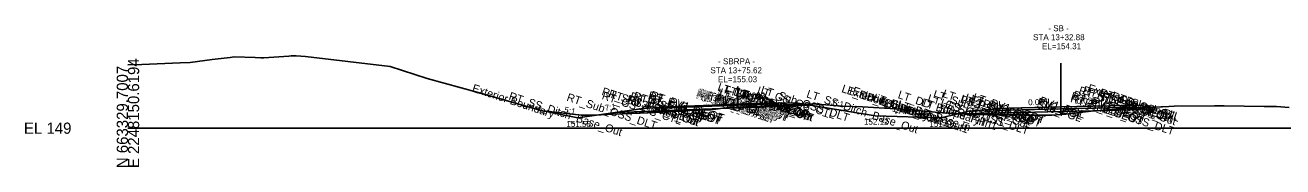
# Model space of a CAD drawing. Extents: x -26 to 2603, y -10 to 9566.
# Drawn here: x -25.7 to 288.7, y 6490.3 to 6525.8 of the extents above; entities that cross this region are included whole.
import ezdxf

# ---------------------------------------------------------------- set-up
doc = ezdxf.new("R2010")
doc.units = 0
for name, color, linetype in [('Default', 7, 'Continuous'), ('Exist Cross Section Cell', 7, 'Continuous'), ('Exist XS Ground Line', 7, 'Continuous'), ('Prop CMT Ditch DDE', 7, 'Continuous'), ('Prop CMT Pvmt Course 1', 7, 'Continuous'), ('Prop CMT Pvmt Course 1 Wedge', 7, 'Continuous'), ('Prop CMT Pvmt Course 2', 7, 'Continuous'), ('Prop CMT Pvmt Course 2 Wedge', 7, 'Continuous'), ('Prop CMT Pvmt Course 3', 7, 'Continuous'), ('Prop CMT Pvmt Surface', 7, 'Continuous'), ('Prop CMT Pvmt Surface Overlay', 7, 'Continuous'), ('Prop CMT Pvmt Surface Shoulder', 7, 'Continuous'), ('Prop CMT Pvmt Wedge Surface 1', 7, 'Continuous'), ('Prop CMT Pvmt Wedge Surface 2', 7, 'Continuous'), ('Prop CMT Shld Paved Course 1', 7, 'Continuous'), ('Prop CMT Shld Paved Course 2', 7, 'Continuous'), ('Prop CMT Shld Paved Course 3', 7, 'Continuous'), ('Prop CMT Slope Grass', 7, 'Continuous'), ('Prop CMT Subgrade Earthwork', 7, 'Continuous'), ('Prop XS Ditch Standard Text', 7, 'Continuous'), ('Prop XS SE Text', 7, 'Continuous'), ('Prop XS Side Slope Text', 7, 'Continuous'), ('Prop XS Vertical Lines Alignments', 7, 'Continuous'), ('Scratch_Level_1', 7, 'Continuous'), ('Scratch_Level_9', 7, 'Continuous')]:
    doc.layers.add(name, color=color, linetype=linetype)

msp = doc.modelspace()

# ---------------------------------------------------------------- linework, layer by layer
at = {"layer": 'Exist Cross Section Cell'}
msp.add_line((0, 6500), (300, 6500), dxfattribs=at)
at = {"layer": 'Exist XS Ground Line'}
for p, q in [((15.53, 6516.46), (21.01, 6517.23)), ((21.01, 6517.23), (25.55, 6517.7)), ((25.55, 6517.7), (26.56, 6517.85)), ((26.56, 6517.85), (31.84, 6517.66)), ((31.84, 6517.66), (33.24, 6517.63)), ((33.24, 6517.63), (34, 6517.63)), ((34, 6517.63), (40.23, 6518.04)), ((40.23, 6518.04), (40.81, 6518.14)), ((40.81, 6518.14), (42.02, 6518.15)), ((42.02, 6518.15), (44.38, 6517.95)), ((44.38, 6517.95), (65.57, 6515.46)), ((0, 6515.82), (3.45, 6515.93)), ((3.45, 6515.93), (13.06, 6516.32)), ((13.06, 6516.32), (15.53, 6516.46)), ((65.57, 6515.46), (74.83, 6512.4)), ((74.83, 6512.4), (87.54, 6508.97)), ((87.54, 6508.97), (102.93, 6504.53)), ((102.93, 6504.53), (103.72, 6504.32)), ((103.72, 6504.32), (113.36, 6503.24)), ((129.93, 6503.88), (135.63, 6504.1)), ((135.63, 6504.1), (137.93, 6504.24)), ((137.93, 6504.24), (139.3, 6504.27)), ((139.3, 6504.27), (140.35, 6504.4)), ((140.35, 6504.4), (145.75, 6504.62)), ((145.75, 6504.62), (148.68, 6505.03)), ((148.68, 6505.03), (152.37, 6505.22)), ((152.37, 6505.22), (153.03, 6505.26)), ((153.03, 6505.26), (164.49, 6505.82)), ((164.49, 6505.82), (170.54, 6506.12)), ((170.54, 6506.12), (172.23, 6505.98)), ((172.23, 6505.98), (178.65, 6505.54)), ((178.65, 6505.54), (183.58, 6505.37)), ((183.58, 6505.37), (194.64, 6504.69)), ((194.64, 6504.69), (195.44, 6504.63)), ((195.44, 6504.63), (203.63, 6503.85)), ((234.4, 6503.48), (240.73, 6504.23)), ((240.73, 6504.23), (241.62, 6504.33)), ((241.62, 6504.33), (242.23, 6504.38)), ((242.23, 6504.38), (248.79, 6504.95)), ((248.79, 6504.95), (258.21, 6505.35)), ((258.21, 6505.35), (258.6, 6505.37)), ((258.6, 6505.37), (260.16, 6505.43)), ((260.16, 6505.43), (261.53, 6505.49)), ((261.53, 6505.49), (271.6, 6505.6)), ((271.6, 6505.6), (273.14, 6505.62)), ((273.14, 6505.62), (273.98, 6505.61)), ((273.98, 6505.61), (283.97, 6505.46)), ((283.97, 6505.46), (285.45, 6505.42)), ((285.45, 6505.42), (286.4, 6505.4)), ((286.4, 6505.4), (287.06, 6505.39)), ((287.06, 6505.39), (290.27, 6505.19)), ((113.36, 6503.24), (116.75, 6503.27)), ((116.75, 6503.27), (121.3, 6503.53)), ((121.3, 6503.53), (129.93, 6503.88)), ((203.63, 6503.85), (209.33, 6503.51)), ((209.33, 6503.51), (210.63, 6503.45)), ((210.63, 6503.45), (215.53, 6503.33)), ((215.53, 6503.33), (222.51, 6503.3)), ((222.51, 6503.3), (224.4, 6503.28)), ((224.4, 6503.28), (230.9, 6503.25)), ((230.9, 6503.25), (234.4, 6503.48))]:
    msp.add_line(p, q, dxfattribs=at)
at = {"layer": 'Prop CMT Ditch DDE'}
for points in [[(207.45, 6503.63), (203.16, 6502.56)], [(207.45, 6503.63), (207.45, 6503.63)]]:
    msp.add_lwpolyline(points, dxfattribs=at)
at = {"layer": 'Prop CMT Pvmt Course 1'}
for points in [[(152.45, 6506.03), (139.55, 6505.53)], [(139.55, 6505.28), (152.45, 6505.78)], [(139.55, 6505.53), (139.55, 6505.28)], [(152.45, 6505.9), (161.05, 6506.24)], [(152.45, 6506.03), (156.75, 6506.19)], [(161.05, 6506.11), (152.45, 6505.78)], [(152.45, 6505.78), (152.45, 6506.03)], [(152.45, 6505.78), (152.45, 6506.03)], [(156.75, 6505.94), (152.45, 6505.78)], [(152.45, 6505.78), (152.45, 6505.9)], [(156.75, 6506.19), (156.75, 6505.94)], [(161.05, 6506.24), (161.05, 6506.11)], [(233.2, 6505.31), (220.12, 6504.98)], [(220.12, 6504.98), (220.12, 6504.48)], [(220.12, 6504.48), (233.2, 6504.81)], [(233.2, 6505.31), (245.2, 6505.61)], [(233.2, 6504.81), (233.2, 6505.31)], [(233.2, 6504.81), (233.2, 6505.31)], [(245.2, 6505.11), (233.2, 6504.81)], [(245.2, 6505.61), (245.2, 6505.11)]]:
    msp.add_lwpolyline(points, dxfattribs=at)
msp.add_lwpolyline([(152.45, 6505.78), (152.45, 6505.9), (152.45, 6505.9), (152.45, 6505.78)], close=True, dxfattribs=at)
at = {"layer": 'Prop CMT Pvmt Course 1 Wedge'}
for points in [[(161.05, 6506.24), (152.45, 6505.9)], [(152.45, 6505.9), (152.45, 6505.9)]]:
    msp.add_lwpolyline(points, dxfattribs=at)
at = {"layer": 'Prop CMT Pvmt Course 2'}
for points in [[(152.45, 6505.78), (139.55, 6505.28)], [(139.55, 6505.28), (139.55, 6504.61)], [(139.55, 6504.61), (152.45, 6505.11)], [(152.45, 6505.78), (156.75, 6505.94)], [(152.45, 6505.11), (152.45, 6505.78)], [(152.45, 6505.11), (152.45, 6505.78)], [(156.75, 6505.28), (152.45, 6505.11)], [(156.75, 6505.94), (156.75, 6505.28)], [(233.2, 6504.81), (220.12, 6504.48)], [(220.12, 6504.48), (220.12, 6503.82)], [(220.12, 6503.82), (233.2, 6504.15)], [(233.2, 6504.81), (245.2, 6505.11)], [(233.2, 6504.15), (233.2, 6504.81)], [(233.2, 6504.15), (233.2, 6504.81)], [(245.2, 6504.45), (233.2, 6504.15)], [(245.2, 6505.11), (245.2, 6504.45)]]:
    msp.add_lwpolyline(points, dxfattribs=at)
at = {"layer": 'Prop CMT Pvmt Course 2 Wedge'}
for points in [[(161.05, 6506.11), (152.45, 6505.78)], [(152.45, 6505.78), (152.45, 6505.78)]]:
    msp.add_lwpolyline(points, dxfattribs=at)
at = {"layer": 'Prop CMT Pvmt Course 3'}
for points in [[(152.45, 6505.11), (139.55, 6504.61)], [(139.55, 6504.6), (152.45, 6505.1)], [(139.55, 6504.61), (139.55, 6504.6)], [(152.45, 6505.11), (156.75, 6505.28)], [(156.75, 6505.27), (152.45, 6505.1)], [(152.45, 6505.1), (152.45, 6505.11)], [(152.45, 6505.1), (152.45, 6505.11)], [(156.75, 6505.28), (156.75, 6505.27)]]:
    msp.add_lwpolyline(points, dxfattribs=at)
at = {"layer": 'Prop CMT Pvmt Surface'}
for points in [[(152.45, 6506.03), (139.55, 6505.53)], [(152.45, 6506.03), (156.75, 6506.19)], [(233.2, 6505.31), (220.12, 6504.98)], [(233.2, 6505.31), (245.2, 6505.61)]]:
    msp.add_lwpolyline(points, dxfattribs=at)
at = {"layer": 'Prop CMT Pvmt Surface Overlay'}
for points in [[(233.2, 6505.31), (220.12, 6504.98)], [(233.2, 6505.31), (245.2, 6505.61)]]:
    msp.add_lwpolyline(points, dxfattribs=at)
at = {"layer": 'Prop CMT Pvmt Surface Shoulder'}
for points in [[(139.55, 6505.53), (135.23, 6505.36)], [(156.75, 6506.19), (161.05, 6506.36)], [(220.12, 6504.98), (218.11, 6504.93)], [(245.2, 6505.61), (251.2, 6505.76)]]:
    msp.add_lwpolyline(points, dxfattribs=at)
at = {"layer": 'Prop CMT Pvmt Wedge Surface 1'}
for points in [[(152.45, 6505.78), (139.55, 6505.28)], [(139.55, 6505.28), (139.55, 6505.53)], [(161.05, 6506.24), (152.45, 6505.9)], [(152.45, 6505.78), (161.05, 6506.11)], [(152.45, 6506.03), (152.45, 6505.78)], [(152.45, 6506.03), (152.45, 6505.78), (152.45, 6505.78), (152.45, 6505.9), (152.45, 6505.9), (152.45, 6505.78)], [(152.45, 6505.78), (156.75, 6505.94)], [(152.45, 6505.9), (152.45, 6505.78)], [(156.75, 6505.94), (156.75, 6506.19)], [(161.05, 6506.11), (161.05, 6506.24)]]:
    msp.add_lwpolyline(points, dxfattribs=at)
at = {"layer": 'Prop CMT Pvmt Wedge Surface 2'}
for points in [[(152.45, 6505.78), (139.55, 6505.28)], [(139.55, 6505.28), (139.55, 6505.53)], [(152.45, 6506.03), (152.45, 6505.78)], [(152.45, 6506.03), (152.45, 6505.78)], [(152.45, 6505.78), (156.75, 6505.94)], [(156.75, 6505.94), (156.75, 6506.19)]]:
    msp.add_lwpolyline(points, dxfattribs=at)
at = {"layer": 'Prop CMT Shld Paved Course 1'}
for points in [[(139.55, 6505.53), (135.23, 6505.36), (134.94, 6505.1)], [(134.94, 6505.1), (139.55, 6505.28)], [(139.55, 6505.28), (139.55, 6505.53)], [(156.75, 6506.19), (161.05, 6506.36), (161.31, 6506.12)], [(156.75, 6505.94), (156.75, 6506.19)], [(161.31, 6506.12), (156.75, 6505.94)], [(220.12, 6504.98), (218.11, 6504.93), (217.6, 6504.42)], [(217.6, 6504.42), (220.12, 6504.48)], [(220.12, 6504.48), (220.12, 6504.98)], [(245.2, 6505.61), (251.2, 6505.76), (251.69, 6505.28)], [(245.2, 6505.11), (245.2, 6505.61)], [(251.69, 6505.28), (245.2, 6505.11)]]:
    msp.add_lwpolyline(points, dxfattribs=at)
at = {"layer": 'Prop CMT Shld Paved Course 2'}
for points in [[(139.55, 6505.28), (134.94, 6505.1), (134.19, 6504.4)], [(134.19, 6504.4), (139.55, 6504.61)], [(139.55, 6504.61), (139.55, 6505.28)], [(156.75, 6505.94), (161.31, 6506.12), (161.99, 6505.48)], [(156.75, 6505.28), (156.75, 6505.94)], [(161.99, 6505.48), (156.75, 6505.28)], [(220.12, 6504.48), (217.6, 6504.42), (217.1, 6504.41), (216.41, 6503.72)], [(220.12, 6503.82), (220.12, 6504.48)], [(245.2, 6505.11), (251.69, 6505.28), (252.19, 6505.29), (252.84, 6504.64)], [(245.2, 6504.45), (245.2, 6505.11)], [(252.84, 6504.64), (245.2, 6504.45)], [(216.41, 6503.72), (220.12, 6503.82)]]:
    msp.add_lwpolyline(points, dxfattribs=at)
at = {"layer": 'Prop CMT Shld Paved Course 3'}
for points in [[(139.55, 6504.61), (134.19, 6504.4), (133.65, 6504.38), (133.63, 6504.37)], [(133.63, 6504.37), (139.55, 6504.6)], [(139.55, 6504.6), (139.55, 6504.61)], [(156.75, 6505.28), (161.99, 6505.48), (162.53, 6505.5), (162.54, 6505.49)], [(162.54, 6505.49), (156.75, 6505.27)], [(156.75, 6505.27), (156.75, 6505.28)]]:
    msp.add_lwpolyline(points, dxfattribs=at)
at = {"layer": 'Prop CMT Slope Grass'}
for points in [[(112.42, 6502.55), (103.72, 6504.32)], [(135.23, 6505.36), (128.75, 6504.93), (112.42, 6502.55)], [(161.05, 6506.36), (167.5, 6506.25), (186.77, 6503.12)], [(210.1, 6504.29), (207.45, 6503.63)], [(218.11, 6504.93), (210.1, 6504.29)], [(251.2, 6505.76), (253.2, 6505.69)], [(253.2, 6505.69), (255.1, 6505.22)], [(186.77, 6503.12), (203.16, 6502.56)]]:
    msp.add_lwpolyline(points, dxfattribs=at)
at = {"layer": 'Prop CMT Subgrade Earthwork'}
for points in [[(133.63, 6504.37), (121.84, 6503.92)], [(139.55, 6504.6), (133.63, 6504.37)], [(152.45, 6505.1), (139.55, 6504.6)], [(152.45, 6505.1), (156.75, 6505.27)], [(156.75, 6505.27), (162.54, 6505.49)], [(162.54, 6505.49), (170.3, 6505.8)], [(233.2, 6504.15), (220.12, 6503.82)], [(233.2, 6504.15), (245.2, 6504.45)], [(245.2, 6504.45), (252.84, 6504.64)], [(252.84, 6504.64), (255.1, 6505.22)], [(216.41, 6503.72), (207.45, 6503.63)], [(220.12, 6503.82), (216.41, 6503.72)]]:
    msp.add_lwpolyline(points, dxfattribs=at)
at = {"layer": 'Prop XS Vertical Lines Alignments'}
for p, q in [((233.19, 6516.31), (233.19, 6503.31)), ((152.46, 6510.44), (152.46, 6506.03))]:
    msp.add_line(p, q, dxfattribs=at)

# ---------------------------------------------------------------- texts
at = {"layer": 'Default'}
msp.add_text('-', height=0.0001, dxfattribs=at).set_placement((0, 6500))
at = {"layer": 'Exist Cross Section Cell'}
for s, p in [('E 2248150.6194', (2.8, 6490)), ('N 663329.7007', (0, 6490))]:
    msp.add_text(s, height=2.8, rotation=90, dxfattribs=at).set_placement(p)
msp.add_text('EL 149', height=2.8, dxfattribs=at).set_placement((-26, 6498.6))
at = {"layer": 'Prop XS Ditch Standard Text'}
for s, p in [('151.55', (109.58, 6500.3)), ('152.12', (183.97, 6500.87)), ('151.56', (200.32, 6500.31))]:
    msp.add_text(s, height=1.5, dxfattribs=at).set_placement(p)
at = {"layer": 'Prop XS SE Text'}
for s, rotation, p in [('0.039', 2.2211, (143.35, 6506.67)), ('0.039', 2.2211, (154.27, 6507.34)), ('0.025', 1.4518, (225.02, 6505.73)), ('0.025', 1.4518, (237.12, 6506.08))]:
    msp.add_text(s, height=1.5, rotation=rotation, dxfattribs=at).set_placement(p)
at = {"layer": 'Prop XS Side Slope Text'}
for s, rotation, p in [('5:1', 348.5205, (108.96, 6503.92)), ('7:1', 8.2976, (119.3, 6504.31)), ('6:1', 350.7646, (176.08, 6505.62)), ('VAR.', 358.0404, (191.28, 6503.61)), ('4:1', 14.0067, (205.81, 6504.02))]:
    msp.add_text(s, height=1.5, rotation=rotation, dxfattribs=at).set_placement(p)
at = {"layer": 'Prop XS Vertical Lines Alignments'}
for s, p in [('STA 13+32.88', (226.24, 6522.03)), ('- SB -', (230.05, 6524.28)), ('- SBRPA -', (147.51, 6516)), ('STA 13+75.62', (145.59, 6513.75))]:
    msp.add_text(s, height=1.5, dxfattribs=at).set_placement(p)
at = {"layer": 'Scratch_Level_1'}
for s, p in [('EL=154.31', (228.47, 6519.78)), ('EL=155.03', (147.49, 6511.5))]:
    msp.add_text(s, height=1.5, dxfattribs=at).set_placement(p)
at = {"layer": 'Scratch_Level_9'}
for s, p in [('Exterior Boundary', (85.87, 6509.2)), ('LT_Sub_Trench_Out', (147.22, 6509.48)), ('LT_PS3_Shelf_Out', (148.9, 6508.93)), ('LT_GS_OS_CTL', (157.09, 6508.63)), ('LT_Sub_OSS_DLT', (158.02, 6508.79)), ('LT_DD_Boundary Out1', (178.22, 6509.08)), ('Exterior Boundary', (179.55, 6508.64)), ('Exterior Boundary', (180.94, 6508.55)), ('RT_Sub_Trench_Out', (237.47, 6508.64)), ('RT_PS2_Shelf_Out', (238.51, 6508.73)), ('Exterior Boundary', (239.72, 6509.22)), ('RT_SS_Ditch_Base_Out', (95.04, 6507.22)), ('RT_Sub_OSS_DLT', (109.51, 6506.93)), ('RT_Sub_Trench_Out', (118.27, 6508.38)), ('RT_GS_OS_CTL', (118.3, 6507.32)), ('RT_PS3_Shelf_Out', (119.97, 6507.83)), ('RT_PS3_OEOP', (124.55, 6506.52)), ('RT_PS2_OEOP', (125.31, 6507.22)), ('RT_PS1_OEOP', (126.13, 6507.3)), ('RT_Sub_OEOT', (129.76, 6506.76)), ('RT_PV2_OEOT', (129.85, 6507.41)), ('RT_PV3_OEOT', (129.85, 6506.75)), ('RT_PV1_OEOT', (130.39, 6507.49)), ('RT_Sub_OEEOP', (141.85, 6507.54)), ('LT_Sub_OEEOP', (141.89, 6507.52)), ('RT_PV2_OEEOP', (141.93, 6508.18)), ('RT_PV3_OEEOP', (141.93, 6507.52)), ('LT_PV2_OEEOP', (141.98, 6508.17)), ('LT_PV3_OEEOP', (141.98, 6507.5)), ('RT_PV1_OEEOP', (142.47, 6508.13)), ('LT_PV1_OEEOP', (142.52, 6508.12)), ('RT_PV2_IEEOP', (142.55, 6507.98)), ('RT_PV1_IEEOP', (143.09, 6507.93)), ('PV2_PGL', (146.35, 6506.73)), ('PV1_PGL', (146.89, 6506.8)), ('LT_Sub_OEOT', (147.01, 6507.42)), ('LT_PV2_OEOT', (147.1, 6508.07)), ('LT_PV3_OEOT', (147.1, 6507.4)), ('LT_PV1_OEOT', (147.64, 6508.14)), ('LT_PV2_IEEOP', (151.19, 6508.3)), ('LT_PS2_OEOP', (151.72, 6508.22)), ('LT_PV1_IEEOP', (151.73, 6508.25)), ('LT_PS1_OEOP', (152, 6508.29)), ('LT_PS3_OEOP', (152.4, 6507.58)), ('LT_SS_Ditch_Base_Out', (169.44, 6507.77)), ('LT_Slope_Cut', (186.16, 6506.83)), ('LT_DD_Base Out1', (188.27, 6505.75)), ('LT_DD_Boundary In1', (192.28, 6507.57)), ('LT_Slope_Fill', (198.13, 6505.64)), ('LT_GS_OS_CTL', (199.69, 6506.67)), ('LT_Sub_Trench_Out', (201.1, 6507.71)), ('LT_Sub_OSS_DLT', (202.9, 6505.53)), ('LT_PS2_Shelf_Out', (203.47, 6507.84)), ('LT_PS2_OEOP', (208.01, 6506.52)), ('LT_PS1_OEOP', (209.06, 6506.86)), ('LT_Sub_OEOT', (210.38, 6505.97)), ('LT_PV2_OEOT', (210.47, 6506.61)), ('LT_PV1_OEOT', (211.01, 6506.93)), ('PV2_PGL', (227.09, 6505.77)), ('PV1_PGL', (227.63, 6506.09)), ('RT_Sub_OEOT', (235.42, 6506.61)), ('RT_PV2_OEOT', (235.5, 6507.25)), ('RT_PV1_OEOT', (236.04, 6507.57)), ('RT_Sub_OSS_DLT', (238.88, 6505.55)), ('RT_PS2_OEOP', (242.05, 6507.39)), ('RT_PS1_OEOP', (242.1, 6507.7)), ('RT_GS_OS_CTL', (242.74, 6508.08)), ('RT_Slope_Fill', (245.74, 6507.25)), ('LT_DD_Base In', (192.13, 6505.14)), ('Sub_PGL', (227, 6505.13))]:
    msp.add_text(s, height=2, rotation=341.787, dxfattribs=at).set_placement(p)

doc.saveas('drawing.dxf')
